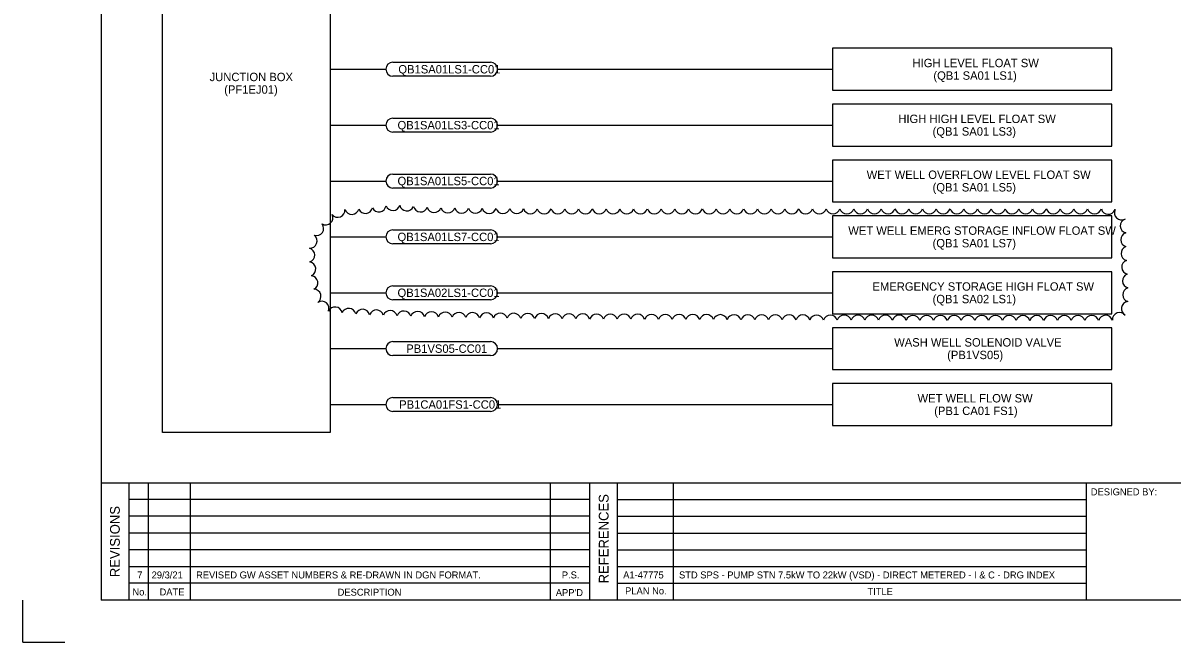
# Model space of a CAD drawing. Extents: x 0 to 841, y 0 to 594.
# Drawn here: x 0 to 411.6, y 0 to 221.6 of the extents above; entities that cross this region are included whole.
import ezdxf

# ---------------------------------------------------------------- set-up
doc = ezdxf.new("R2010")
doc.units = 0
for name, color, linetype in [('A1BORDER', 7, 'Continuous'), ('INSTALLED', 7, 'Continuous'), ('Level 1', 7, 'Continuous')]:
    doc.layers.add(name, color=color, linetype=linetype)

msp = doc.modelspace()

# ---------------------------------------------------------------- linework, layer by layer
at = {"layer": 'A1BORDER'}
for p, q in [((28, 581), (28, 15)), ((28, 57), (829, 57)), ((38, 15), (38, 57)), ((45, 15), (45, 57)), ((60, 15), (60, 57)), ((189, 15), (189, 57)), ((203, 15), (203, 57)), ((213, 15), (213, 57)), ((233, 15), (233, 57)), ((381, 15), (381, 57)), ((203, 51), (38, 51)), ((213, 51), (381, 51)), ((203, 45), (38, 45)), ((213, 45), (381, 45)), ((203, 39), (38, 39)), ((213, 39), (381, 39)), ((203, 33), (38, 33)), ((213, 33), (381, 33)), ((38, 27), (203, 27)), ((213, 27), (381, 27)), ((203, 21), (38, 21)), ((213, 21), (381, 21)), ((0, 0), (0, 15)), ((829, 15), (28, 15)), ((0, 0), (15, 0))]:
    msp.add_line(p, q, dxfattribs=at)
at = {"layer": 'INSTALLED'}
for p, q in [((132.5, 207.5), (167.5, 207.5)), ((110, 205), (130, 205)), ((167.5, 202.5), (132.5, 202.5)), ((170, 205), (290, 205)), ((132.5, 187.5), (167.5, 187.5)), ((110, 185), (130, 185)), ((167.5, 182.5), (132.5, 182.5)), ((170, 185), (290, 185)), ((110, 165), (130, 165)), ((132.5, 167.5), (167.5, 167.5)), ((170, 165), (290, 165)), ((167.5, 162.5), (132.5, 162.5)), ((110, 145), (130, 145)), ((132.5, 147.5), (167.5, 147.5)), ((170, 145), (290, 145)), ((167.5, 142.5), (132.5, 142.5)), ((110, 125), (130, 125)), ((132.5, 127.5), (167.5, 127.5)), ((170, 125), (290, 125)), ((167.5, 122.5), (132.5, 122.5)), ((132.5, 107.5), (167.5, 107.5)), ((110, 105), (130, 105)), ((170, 105), (290, 105)), ((167.5, 102.5), (132.5, 102.5)), ((132.5, 87.5), (167.5, 87.5)), ((110, 85), (130, 85)), ((167.5, 82.5), (132.5, 82.5)), ((170, 85), (290, 85))]:
    msp.add_line(p, q, dxfattribs=at)
for points in [[(50, 565), (110, 565), (110, 75), (50, 75)], [(290, 197.5), (390, 197.5), (390, 212.5), (290, 212.5)], [(290, 177.5), (390, 177.5), (390, 192.5), (290, 192.5)], [(290, 157.5), (390, 157.5), (390, 172.5), (290, 172.5)], [(290, 137.5), (390, 137.5), (390, 152.5), (290, 152.5)], [(290, 117.5), (390, 117.5), (390, 132.5), (290, 132.5)], [(290, 97.5), (390, 97.5), (390, 112.5), (290, 112.5)], [(290, 77.5), (390, 77.5), (390, 92.5), (290, 92.5)]]:
    msp.add_lwpolyline(points, close=True, dxfattribs=at)
for centre, start, end in [((132.5, 205), 90, 270), ((167.5, 205), 270, 90), ((132.5, 185), 90, 270), ((167.5, 185), 270, 90), ((132.5, 165), 90, 270), ((167.5, 165), 270, 90), ((132.5, 145), 90, 270), ((167.5, 145), 270, 90), ((132.5, 125), 90, 270), ((167.5, 125), 270, 90), ((132.5, 105), 90, 270), ((167.5, 105), 270, 90), ((132.5, 85), 90, 270), ((167.5, 85), 270, 90)]:
    msp.add_arc(centre, 2.5, start, end, dxfattribs=at)
at = {"layer": 'Level 1'}
for centre, radius, start, end in [((108.43, 151.87), 2.58, 240.6307, 25.6307), ((112.77, 154.6), 2.58, 218.6406, 3.6406), ((117.79, 155.63), 2.58, 199.582, 344.582), ((122.66, 155.95), 2.58, 202.9312, 347.9312), ((127.5, 156.54), 2.58, 206.0677, 351.0677), ((132.49, 157.02), 2.58, 199.7374, 344.7374), ((137.5, 156.89), 2.58, 192.3225, 337.3225), ((142.39, 156.52), 2.59, 194.0582, 339.0582), ((147.29, 156.3), 2.58, 195.8539, 340.8539), ((152.21, 156.18), 2.58, 196.3684, 341.3684), ((157.13, 156.1), 2.58, 196.6458, 341.6458), ((162.06, 156.03), 2.58, 196.8263, 341.8263), ((166.99, 155.98), 2.58, 196.9559, 341.9559), ((171.91, 155.94), 2.58, 197.0547, 342.0547), ((176.84, 155.9), 2.58, 197.1334, 342.1334), ((181.76, 155.87), 2.58, 197.1979, 342.1979), ((186.69, 155.85), 2.58, 197.2521, 342.2521), ((191.62, 155.83), 2.58, 197.2984, 342.2984), ((196.55, 155.81), 2.58, 197.3386, 342.3386), ((201.47, 155.8), 2.58, 197.3739, 342.3739), ((206.4, 155.79), 2.58, 197.4052, 342.4052), ((211.33, 155.78), 2.58, 197.4333, 342.4333), ((216.26, 155.78), 2.58, 197.4586, 342.4586), ((221.18, 155.78), 2.58, 197.4816, 342.4816), ((226.11, 155.78), 2.58, 197.4986, 342.4986), ((231.04, 155.78), 2.58, 197.5, 342.5), ((235.97, 155.78), 2.58, 197.5, 342.5), ((240.89, 155.78), 2.58, 197.5, 342.5), ((245.82, 155.78), 2.58, 197.5, 342.5), ((250.75, 155.78), 2.58, 197.5, 342.5), ((255.68, 155.78), 2.58, 197.5, 342.5), ((260.61, 155.78), 2.58, 197.5, 342.5), ((265.53, 155.78), 2.58, 197.5, 342.5), ((270.46, 155.78), 2.58, 197.5, 342.5), ((275.39, 155.78), 2.58, 197.5, 342.5), ((280.32, 155.78), 2.58, 197.5, 342.5), ((285.25, 155.78), 2.58, 197.5, 342.5), ((290.17, 155.78), 2.58, 197.5, 342.5), ((295.1, 155.78), 2.58, 197.5, 342.5), ((300.03, 155.78), 2.58, 197.5, 342.5), ((304.96, 155.78), 2.58, 197.5, 342.5), ((309.88, 155.78), 2.58, 197.5, 342.5), ((314.81, 155.78), 2.58, 197.5, 342.5), ((319.74, 155.78), 2.58, 197.5, 342.5), ((324.67, 155.78), 2.58, 197.5, 342.5), ((329.6, 155.78), 2.58, 197.5, 342.5), ((334.52, 155.78), 2.58, 197.5, 342.5), ((339.45, 155.78), 2.58, 197.5, 342.5), ((344.38, 155.78), 2.58, 197.5, 342.5), ((349.31, 155.78), 2.58, 197.5, 342.5), ((354.23, 155.78), 2.58, 197.5, 342.5), ((359.16, 155.78), 2.58, 197.5, 342.5), ((364.09, 155.78), 2.58, 197.5, 342.5), ((369.02, 155.78), 2.58, 197.5, 342.5), ((373.95, 155.78), 2.58, 197.5, 342.5), ((378.87, 155.78), 2.58, 197.5, 342.5), ((383.8, 155.78), 2.58, 197.5, 342.5), ((388.76, 155.67), 2.58, 194.9744, 339.9744), ((393.5, 153.63), 2.58, 153.5701, 298.5701), ((105.12, 148.04), 2.58, 252.6704, 37.6704), ((395.64, 148.94), 2.58, 110.3956, 255.3956), ((102.77, 143.52), 2.58, 267.5419, 52.5419), ((395.79, 143.99), 2.58, 108.1178, 253.1178), ((101.95, 138.46), 2.58, 289.0365, 74.0365), ((395.91, 139.08), 2.58, 109.7025, 254.7025), ((102.31, 133.48), 2.58, 294.2255, 79.2255), ((396.15, 134.18), 2.58, 110.8853, 255.8853), ((103.02, 128.56), 2.58, 297.1337, 82.1337), ((396.41, 129.25), 2.58, 110.0871, 255.0871), ((104.17, 123.68), 2.58, 304.4573, 89.4573), ((396.5, 124.28), 2.58, 107.1492, 252.1492), ((107.04, 119.38), 2.58, 337.8525, 122.8525), ((111.78, 117.34), 2.58, 10.5505, 155.5505), ((116.72, 116.85), 2.58, 13.1939, 158.1939), ((396.04, 119.26), 2.58, 97.3774, 242.3774), ((121.65, 116.52), 2.58, 14.2719, 159.2719), ((126.58, 116.27), 2.58, 14.9017, 159.9017), ((131.51, 116.07), 2.58, 15.3279, 160.3279), ((136.44, 115.89), 2.58, 15.6409, 160.6409), ((141.37, 115.74), 2.58, 15.8834, 160.8834), ((146.3, 115.61), 2.58, 16.0785, 161.0785), ((151.23, 115.5), 2.58, 16.2399, 161.2399), ((156.15, 115.4), 2.58, 16.3762, 161.3762), ((161.08, 115.3), 2.58, 16.4934, 161.4934), ((166.01, 115.22), 2.58, 16.5955, 161.5955), ((170.94, 115.15), 2.58, 16.6856, 161.6856), ((175.87, 115.08), 2.58, 16.7658, 161.7658), ((180.8, 115.02), 2.58, 16.8378, 161.8378), ((185.72, 114.97), 2.58, 16.9029, 161.9029), ((190.65, 114.92), 2.58, 16.9621, 161.9621), ((195.58, 114.87), 2.58, 17.0163, 162.0163), ((200.51, 114.84), 2.58, 17.0662, 162.0662), ((205.44, 114.8), 2.58, 17.1123, 162.1123), ((210.37, 114.77), 2.58, 17.155, 162.155), ((215.3, 114.74), 2.58, 17.1948, 162.1948), ((220.22, 114.72), 2.58, 17.232, 162.232), ((225.15, 114.69), 2.58, 17.2625, 162.2625), ((230.08, 114.67), 2.58, 17.2675, 162.2675), ((235.01, 114.65), 2.58, 17.2688, 162.2688), ((239.93, 114.63), 2.58, 17.2701, 162.2701), ((244.86, 114.61), 2.58, 17.2715, 162.2715), ((249.79, 114.59), 2.58, 17.2729, 162.2729), ((254.72, 114.58), 2.58, 17.2745, 162.2745), ((259.65, 114.56), 2.58, 17.2762, 162.2762), ((264.57, 114.54), 2.58, 17.278, 162.278), ((269.5, 114.52), 2.58, 17.2799, 162.2799), ((274.43, 114.5), 2.58, 17.282, 162.282), ((279.36, 114.48), 2.58, 17.2842, 162.2842), ((284.29, 114.46), 2.58, 17.2866, 162.2866), ((289.21, 114.44), 2.58, 17.2893, 162.2893), ((294.14, 114.43), 2.58, 17.2922, 162.2922), ((299.07, 114.41), 2.58, 17.2954, 162.2954), ((304, 114.39), 2.58, 17.299, 162.299), ((308.92, 114.37), 2.58, 17.3031, 162.3031), ((313.85, 114.36), 2.58, 17.3076, 162.3076), ((318.78, 114.34), 2.58, 17.3129, 162.3129), ((323.71, 114.32), 2.58, 17.319, 162.319), ((328.64, 114.31), 2.58, 17.3261, 162.3261), ((333.56, 114.29), 2.58, 17.3348, 162.3348), ((338.49, 114.28), 2.58, 17.3455, 162.3455), ((343.42, 114.27), 2.58, 17.3594, 162.3594), ((348.35, 114.26), 2.58, 17.378, 162.378), ((353.28, 114.25), 2.58, 17.4054, 162.4054), ((358.2, 114.24), 2.58, 17.4515, 162.4515), ((363.13, 114.24), 2.58, 17.5323, 162.5323), ((368.06, 114.25), 2.58, 17.572, 162.572), ((372.99, 114.25), 2.58, 17.6127, 162.6127), ((377.92, 114.27), 2.58, 17.6811, 162.6811), ((382.85, 114.29), 2.58, 17.8396, 162.8396), ((387.8, 114.38), 2.58, 19.3015, 164.3015), ((392.81, 115.38), 2.58, 38.1195, 183.1195)]:
    msp.add_arc(centre, radius, start, end, dxfattribs=at)

# ---------------------------------------------------------------- texts
at = {"layer": 'A1BORDER'}
for s, p in [('DESIGNED BY:', (382.5, 52.5)), ('No.', (39.21, 16.65)), ('DATE', (48.92, 16.65)), ('DESCRIPTION', (112.71, 16.57)), ("APP'D", (190.85, 16.44)), ('PLAN No.', (215.69, 17.06)), ('TITLE', (302.5, 16.81))]:
    msp.add_text(s, height=2.5, dxfattribs=at).set_placement(p)
for s, p in [('REFERENCES', (209.76, 20.96)), ('REVISIONS', (34.68, 23.2))]:
    msp.add_text(s, height=3.5, rotation=90, dxfattribs=at).set_placement(p)
at = {"layer": 'INSTALLED'}
for s, p in [('QB1SA01LS1-CC01', (134.46, 203.5)), ('HIGH LEVEL FLOAT SW', (318.63, 205.75)), ('JUNCTION BOX', (66.85, 200.75)), ('(QB1 SA01 LS1)', (326.1, 201.25)), ('(PF1EJ01)', (72.08, 196.25)), ('QB1SA01LS3-CC01', (134.16, 183.5)), ('HIGH HIGH LEVEL FLOAT SW', (313.55, 185.75)), ('(QB1 SA01 LS3)', (325.81, 181.25)), ('WET WELL OVERFLOW LEVEL FLOAT SW', (302.2, 165.75)), ('QB1SA01LS5-CC01', (134.16, 163.5)), ('(QB1 SA01 LS5)', (325.81, 161.25)), ('WET WELL EMERG STORAGE INFLOW FLOAT SW', (295.62, 145.75)), ('QB1SA01LS7-CC01', (134.16, 143.5)), ('(QB1 SA01 LS7)', (325.81, 141.25)), ('EMERGENCY STORAGE HIGH FLOAT SW', (304.29, 125.75)), ('QB1SA02LS1-CC01', (134.16, 123.5)), ('(QB1 SA02 LS1)', (325.81, 121.25)), ('WASH WELL SOLENOID VALVE', (312.06, 105.75)), ('PB1VS05-CC01', (137.3, 103.5)), ('(PB1VS05)', (331.04, 101.25)), ('PB1CA01FS1-CC01', (134.76, 83.5)), ('WET WELL FLOW SW', (320.43, 85.75)), ('(PB1 CA01 FS1)', (326.4, 81.25))]:
    msp.add_text(s, height=3, dxfattribs=at).set_placement(p)
at = {"layer": 'Level 1'}
for s, p in [('7', (40.94, 22.75)), ('29/3/21', (46.09, 22.75)), ('REVISED GW ASSET NUMBERS & RE-DRAWN IN DGN FORMAT.', (62, 22.75)), ('P.S.', (193.02, 22.75)), ('A1-47775', (215, 22.75)), ('STD SPS - PUMP STN 7.5kW TO 22kW (VSD) - DIRECT METERED - I & C - DRG INDEX', (235, 22.75))]:
    msp.add_text(s, height=2.5, dxfattribs=at).set_placement(p)

doc.saveas('drawing.dxf')
